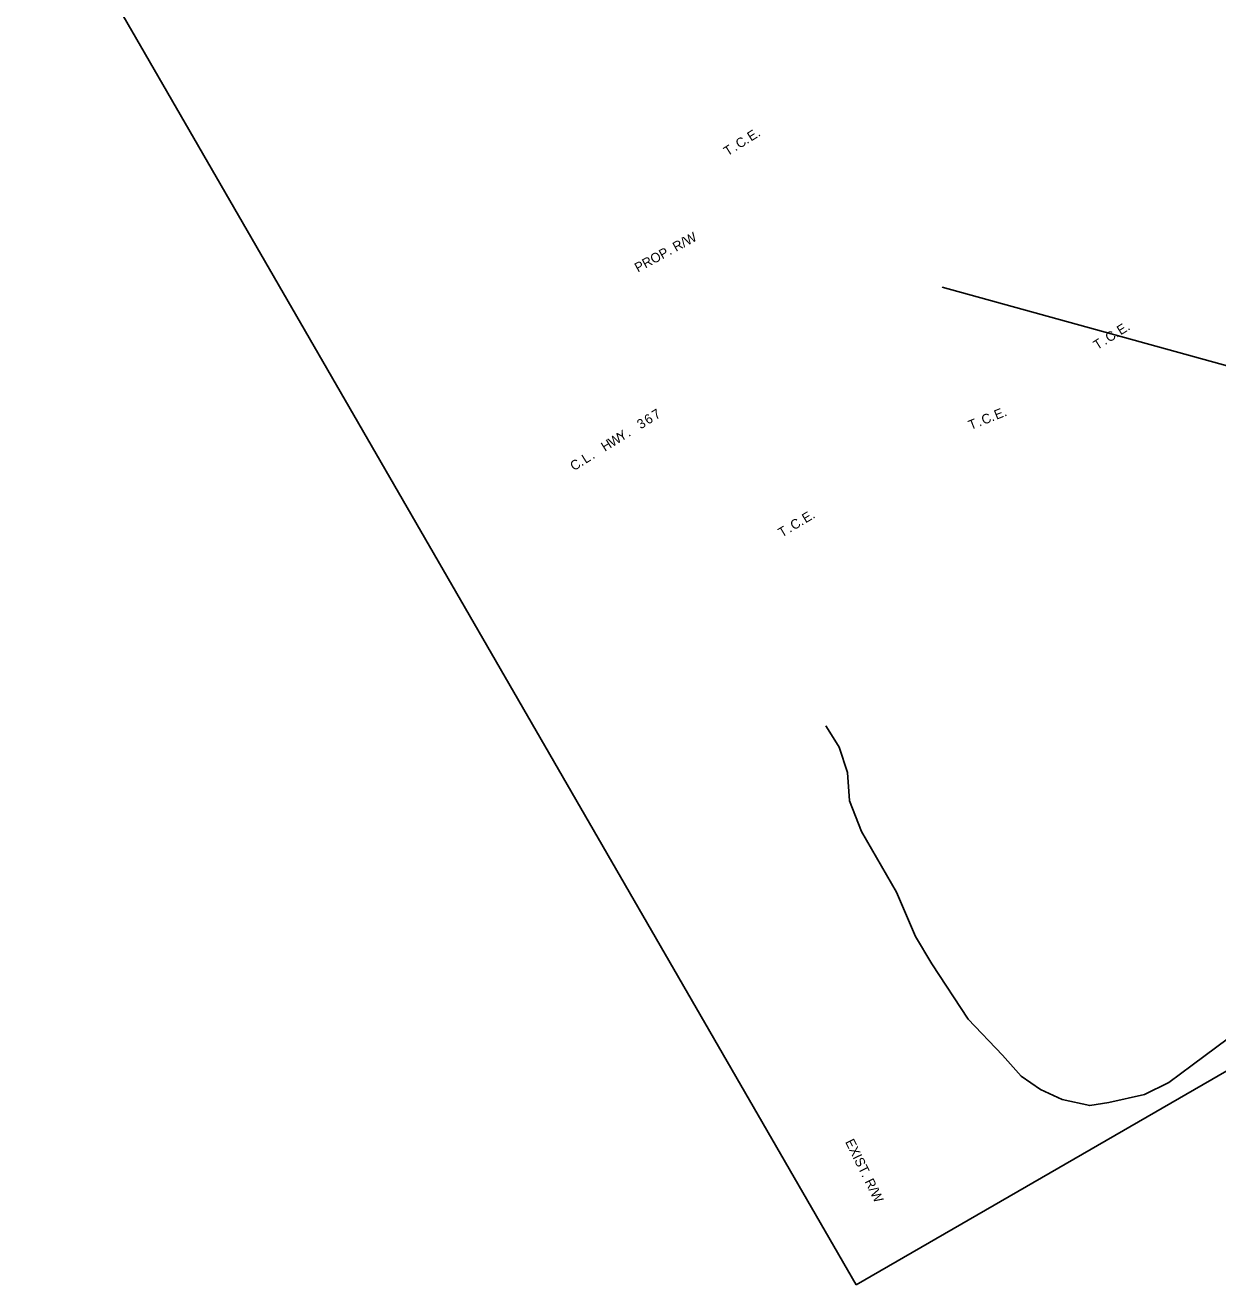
# Model space of a CAD drawing. Extents: x 1293524 to 1295623, y 222963 to 224839.
# Drawn here: x 1293524 to 1294272, y 222963 to 223753 of the extents above; entities that cross this region are included whole.
import ezdxf

# ---------------------------------------------------------------- set-up
doc = ezdxf.new("R2010")
doc.units = 0
for name, color, linetype in [('10Tan10', 7, 'Continuous'), ('Default', 7, 'Continuous'), ('G-No Plot-Border-1', 7, 'Continuous'), ('R_Draft', 7, 'Continuous'), ('S_TREE', 7, 'Continuous')]:
    doc.layers.add(name, color=color, linetype=linetype)

msp = doc.modelspace()

# ---------------------------------------------------------------- linework, layer by layer
at = {"layer": 'G-No Plot-Border-1'}
msp.add_lwpolyline([(1294045.04, 222962.86), (1293523.88, 223865.53), (1294561.39, 224464.54), (1294586.16, 224421.63), (1294757.85, 224520.75), (1294765.6, 224507.33), (1294827.61, 224543.13), (1294901.36, 224415.39), (1295011.78, 224479.14), (1295426.66, 223760.54)], close=True, dxfattribs=at)
msp.add_lwpolyline([(1294045.04, 222962.86), (1293523.88, 223865.53), (1294561.39, 224464.54), (1294586.16, 224421.63), (1294757.85, 224520.75), (1294765.6, 224507.33), (1294827.61, 224543.13), (1294901.36, 224415.39), (1295011.78, 224479.14), (1295426.66, 223760.54)], close=True, dxfattribs=at)
msp.add_lwpolyline([(1294045.04, 222962.86), (1293523.88, 223865.53), (1294561.39, 224464.54), (1294586.16, 224421.63), (1294757.85, 224520.75), (1294765.6, 224507.33), (1294827.61, 224543.13), (1294901.36, 224415.39), (1295011.78, 224479.14), (1295426.66, 223760.54)], close=True, dxfattribs=at)
msp.add_lwpolyline([(1294045.04, 222962.86), (1293523.88, 223865.53), (1294561.39, 224464.54), (1294586.16, 224421.63), (1294757.85, 224520.75), (1294765.6, 224507.33), (1294827.61, 224543.13), (1294901.36, 224415.39), (1295011.78, 224479.14), (1295426.66, 223760.54)], close=True, dxfattribs=at)
at = {"layer": 'S_TREE'}
for points in [[(1294443.51, 223493.56), (1294098.95, 223588.59)], [(1294443.51, 223493.56), (1294098.95, 223588.59)], [(1294026.12, 223313.39), (1294026.44, 223312.93), (1294034.41, 223300.06), (1294039.65, 223284.29), (1294040.93, 223266.46), (1294048.46, 223247.28), (1294070.41, 223209.15), (1294082.4, 223181.33), (1294092.61, 223164.13), (1294115.34, 223129.4), (1294136.94, 223106.87), (1294148.52, 223093.75), (1294160.78, 223085.28), (1294174.29, 223079.08), (1294191.59, 223075.33), (1294203.5, 223077.21), (1294225.94, 223082.16), (1294241.14, 223089.78), (1294255.85, 223100.7), (1294278.59, 223117.58)], [(1294026.12, 223313.39), (1294026.44, 223312.93), (1294034.41, 223300.06), (1294039.65, 223284.29), (1294040.93, 223266.46), (1294048.46, 223247.28), (1294070.41, 223209.15), (1294082.4, 223181.33), (1294092.61, 223164.13), (1294115.34, 223129.4), (1294136.94, 223106.87), (1294148.52, 223093.75), (1294160.78, 223085.28), (1294174.29, 223079.08), (1294191.59, 223075.33), (1294203.5, 223077.21), (1294225.94, 223082.16), (1294241.14, 223089.78), (1294255.85, 223100.7), (1294278.59, 223117.58)]]:
    msp.add_lwpolyline(points, dxfattribs=at)

# ---------------------------------------------------------------- texts
at = {"layer": '10Tan10'}
for s, rotation, p in [('PROP. R/W', 28.60191, (1293908.19, 223597.75)), ('EXIST. R/W', 296.21548, (1294038.04, 223052.53))]:
    msp.add_text(s, height=6, rotation=rotation, dxfattribs=at).set_placement(p)
at = {"layer": 'Default'}
for s, p in [('3', (1293909.96, 223499.39)), ('6', (1293914.53, 223502.25)), ('7', (1293919.33, 223505.25)), ('Y', (1293897.5, 223491.61)), ('H', (1293887.48, 223485.35)), ('W', (1293892.05, 223488.2)), ('.', (1293902.39, 223494.66)), ('L', (1293875.34, 223477.76)), ('C', (1293868.05, 223473.21)), ('.', (1293872.86, 223476.21)), ('.', (1293879.91, 223480.62))]:
    msp.add_text(s, height=6, rotation=31.99396, dxfattribs=at).set_placement(p)
at = {"layer": 'R_Draft'}
for s, rotation, p in [('C', 32.15368, (1293971.85, 223675.36)), ('E', 32.15368, (1293979.13, 223679.94)), ('.', 32.15368, (1293976.65, 223678.38)), ('.', 32.15368, (1293983.69, 223682.8)), ('T', 32.15368, (1293964.41, 223670.68)), ('.', 32.15368, (1293969.37, 223673.8)), ('E', 32.15368, (1294210.99, 223558.38)), ('.', 32.15368, (1294215.55, 223561.24)), ('T', 32.15368, (1294196.27, 223549.12)), ('.', 32.15368, (1294201.23, 223552.24)), ('C', 32.15368, (1294203.71, 223553.8)), ('.', 32.15368, (1294208.51, 223556.82)), ('T', 21.6622, (1294116.92, 223499.02)), ('C', 21.6622, (1294125.09, 223502.27)), ('E', 21.6622, (1294133.08, 223505.44)), ('.', 21.6622, (1294138.09, 223507.43)), ('.', 21.6622, (1294122.37, 223501.18)), ('.', 21.6622, (1294130.36, 223504.36)), ('C', 30.9348, (1294005.99, 223436.04)), ('E', 30.9348, (1294013.37, 223440.46)), ('.', 30.9348, (1294017.99, 223443.23)), ('T', 30.9348, (1293998.46, 223431.52)), ('.', 30.9348, (1294003.48, 223434.53)), ('.', 30.9348, (1294010.86, 223438.95))]:
    msp.add_text(s, height=6, rotation=rotation, dxfattribs=at).set_placement(p)

doc.saveas('drawing.dxf')
